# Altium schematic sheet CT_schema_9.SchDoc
size 274 x 160 mm
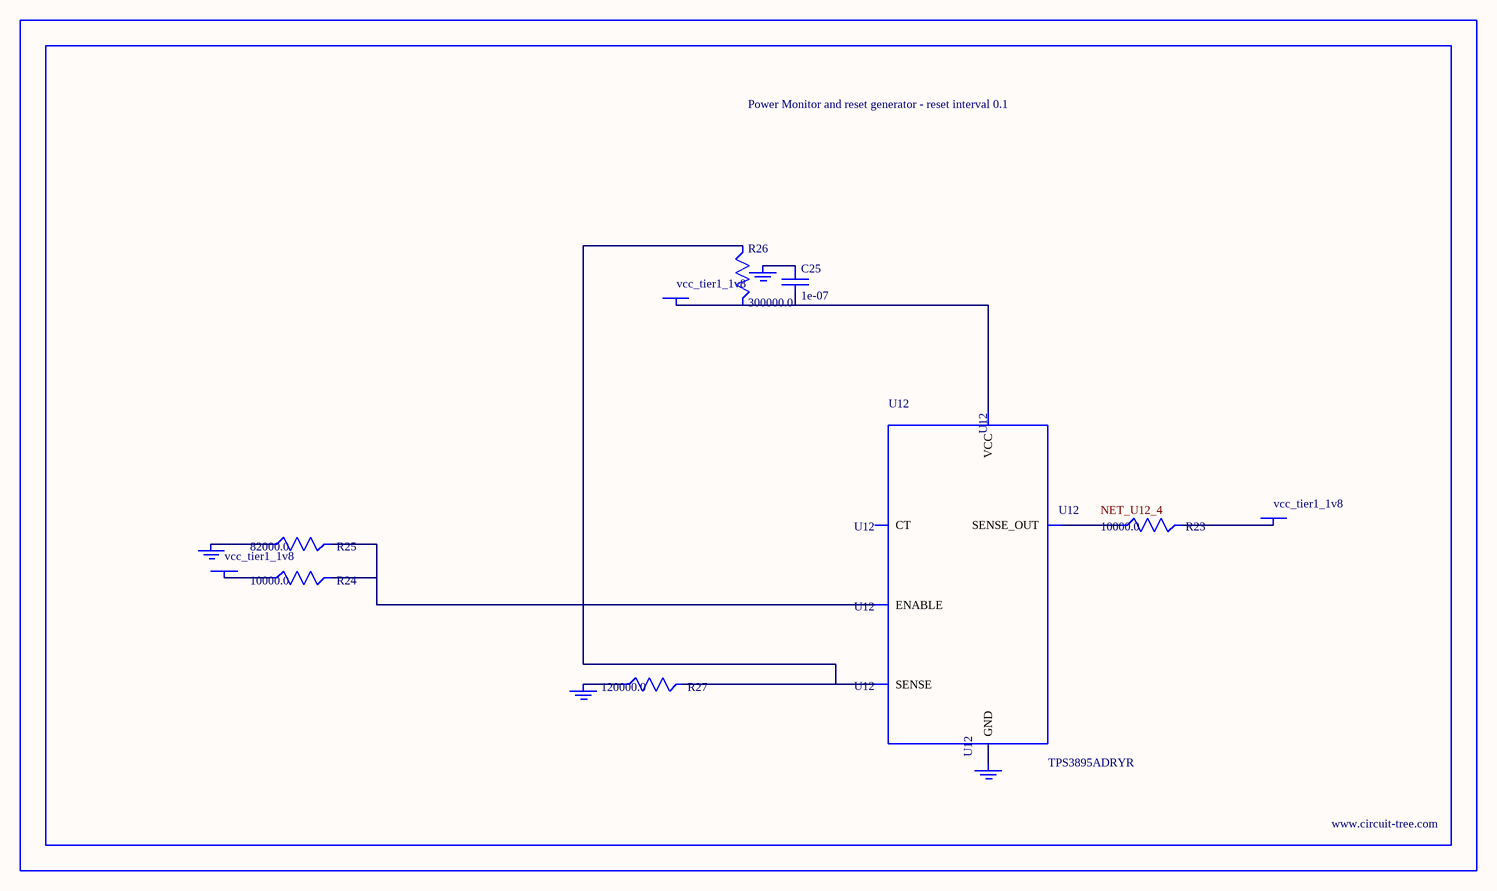
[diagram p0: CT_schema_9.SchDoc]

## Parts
BORDER8  (no value)
C25  1e-07  [C0402]
GND_INSTANCE_8_0  (no value)
GND_INSTANCE_8_1  (no value)
GND_INSTANCE_8_2  (no value)
GND_INSTANCE_8_3  (no value)
POWER_INSTANCE_8_0  vcc_tier1_1v8
POWER_INSTANCE_8_1  vcc_tier1_1v8
POWER_INSTANCE_8_2  vcc_tier1_1v8
R23  10000.0  [R0603]
R24  10000.0  [R0603]
R25  82000.0  [R0603]
R26  300000.0  [R0603]
R27  120000.0  [R0603]
U12  TPS3895ADRYR  [SON-6]

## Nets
NetC25_1: C25.1 GND_INSTANCE_8_2.0(GND)
NetC25_2: C25.2 POWER_INSTANCE_8_2.0(PWR) R26.2 U12.6(VCC)
NetGND_INSTANCE_8_0_0: GND_INSTANCE_8_0.0(GND) R25.1
NetGND_INSTANCE_8_1_0: GND_INSTANCE_8_1.0(GND) R27.1
NetGND_INSTANCE_8_3_0: GND_INSTANCE_8_3.0(GND) U12.2(GND)
NetPOWER_INSTANCE_8_0_0: POWER_INSTANCE_8_0.0(PWR) R24.1
NetPOWER_INSTANCE_8_1_0: POWER_INSTANCE_8_1.0(PWR) R23.2
NetR23_1: R23.1 U12.4(SENSE_OUT)
NetR24_2: R24.2 R25.2 U12.1(ENABLE)
NetR26_1: R26.1 R27.2 U12.3(SENSE)

Not connected (* = marked no-connect by the designer): U12 5(CT)

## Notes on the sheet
- Labels drawn without touching a wire or pin: NET_U12_4

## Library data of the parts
BORDER8 = BORDER_PAGE8
C25 = C0402C104K3RACTU
GND_INSTANCE_8_0-GND_INSTANCE_8_3 = GND
POWER_INSTANCE_8_0-POWER_INSTANCE_8_2 = PWR
R23 R24 = RC0603JR-0710KL
R25 = RC0603JR-0782KL
R26 = RC0603JR-07300KL
R27 = RC0603JR-07120KL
